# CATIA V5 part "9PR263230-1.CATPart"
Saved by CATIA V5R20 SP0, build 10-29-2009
Part number: 9PR263230-1
Revision: ANY
Definition: UNKNOWN
Nomenclature: 9PR263230-1
Source: Unknown
Bounding box of the stored display mesh (mm): x 0 to 32, y -12.803 to 12.803, z -13 to 13
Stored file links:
  C:\Users\Utente\Desktop\IO LAVORO\3D X SITO CF\CUMSA\3D files PR.233230\PR 263230\9PR263230-1.CATPart
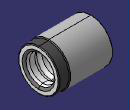
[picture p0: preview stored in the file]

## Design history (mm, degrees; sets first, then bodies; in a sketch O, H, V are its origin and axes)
Body1 "Chaflán3" (main body)
  Solid1: solid without history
